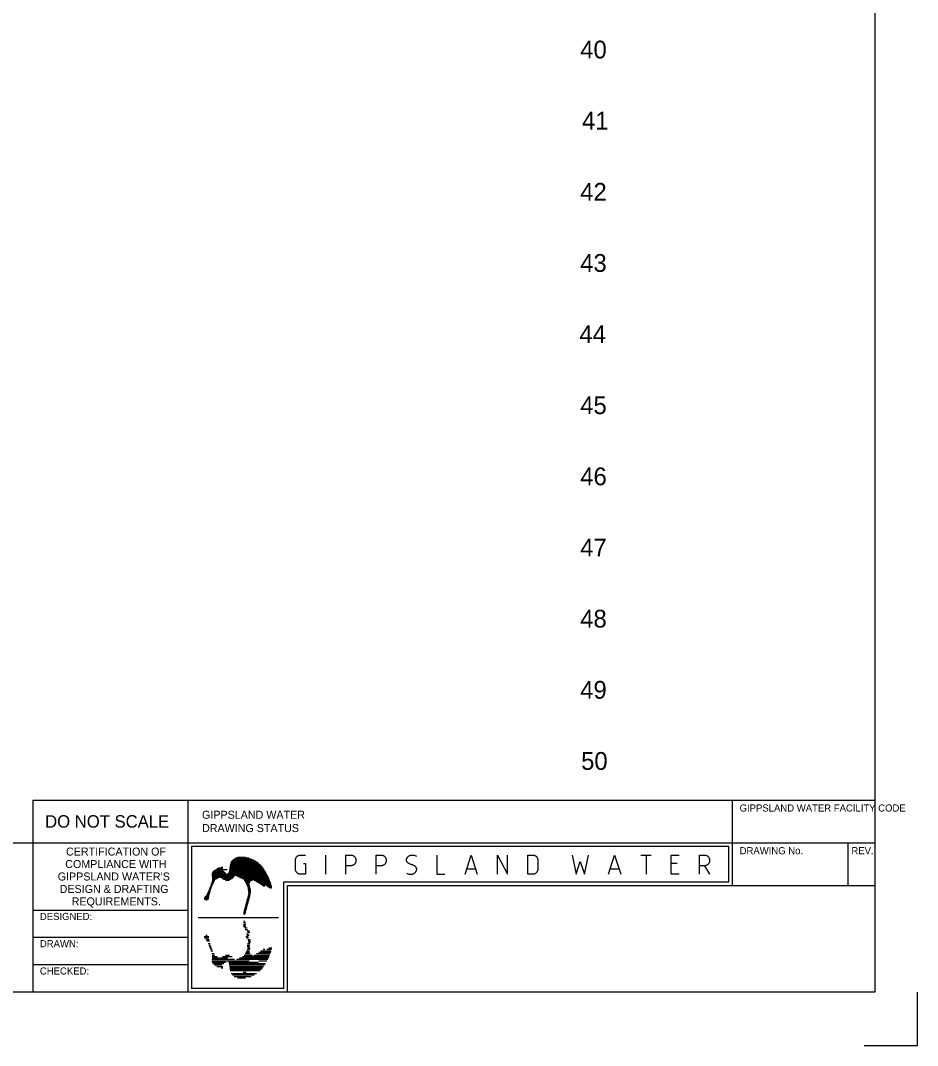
# Model space of a CAD drawing. Extents: x 0 to 841, y 0 to 594.
# Drawn here: x 589 to 841, y 0 to 288.2 of the extents above; entities that cross this region are included whole.
import ezdxf

# ---------------------------------------------------------------- set-up
doc = ezdxf.new("R2010")
doc.units = 0
doc.layers.add('A1BORDER', color=7, linetype='Continuous')
doc.layers.add('Level 1', color=7, linetype='Continuous')

msp = doc.modelspace()

# ---------------------------------------------------------------- linework, layer by layer
at = {"layer": 'A1BORDER'}
for p, q in [((829, 581), (829, 15)), ((592.5, 69), (592.5, 15)), ((592.5, 69), (829, 69)), ((636, 69), (636, 15)), ((789, 45), (789, 69)), ((28, 57), (829, 57)), ((637, 56), (788, 56)), ((637, 56), (637, 16)), ((788, 46), (788, 56)), ((821.5, 45), (821.5, 57)), ((648.37, 51.92), (655, 51.92)), ((648.53, 52.12), (654.64, 52.12)), ((648.74, 52.32), (654.24, 52.32)), ((649.02, 52.52), (653.76, 52.52)), ((649.39, 52.72), (653.15, 52.72)), ((650.01, 52.92), (652.2, 52.92)), ((643.26, 49.12), (645.9, 49.12)), ((643.54, 49.32), (645.57, 49.32)), ((643.85, 49.52), (647.09, 49.52)), ((644.18, 49.72), (645.89, 49.72)), ((644.54, 49.92), (645.36, 49.92)), ((645.37, 50.12), (645.86, 50.12)), ((647.63, 49.12), (657.68, 49.12)), ((647.66, 49.32), (657.57, 49.32)), ((647.69, 49.52), (657.44, 49.52)), ((647.71, 49.72), (657.31, 49.72)), ((647.75, 49.92), (657.17, 49.92)), ((647.78, 50.12), (657.02, 50.12)), ((647.81, 50.32), (656.86, 50.32)), ((647.85, 50.52), (656.69, 50.52)), ((647.88, 50.72), (656.5, 50.72)), ((647.91, 50.92), (656.3, 50.92)), ((647.96, 51.12), (656.08, 51.12)), ((648.03, 51.32), (655.85, 51.32)), ((648.12, 51.52), (655.59, 51.52)), ((648.23, 51.72), (655.31, 51.72)), ((642.73, 48.12), (658.25, 48.12)), ((642.74, 47.92), (658.35, 47.92)), ((642.75, 48.32), (646.79, 48.32)), ((642.79, 47.72), (649.08, 47.72)), ((642.79, 46.12), (643.4, 46.12)), ((642.81, 48.52), (646.55, 48.52)), ((642.83, 47.52), (648.95, 47.52)), ((642.84, 46.32), (643.5, 46.32)), ((642.85, 47.31), (644.88, 47.31)), ((642.87, 47.12), (644.57, 47.12)), ((642.87, 46.52), (643.6, 46.52)), ((642.88, 46.92), (644.23, 46.92)), ((642.88, 46.72), (643.83, 46.72)), ((642.9, 48.72), (646.37, 48.72)), ((643.04, 48.92), (646.16, 48.92)), ((645.14, 47.31), (648.83, 47.31)), ((645.49, 47.12), (648.67, 47.12)), ((645.76, 46.92), (648.42, 46.92)), ((646.05, 46.72), (648.11, 46.72)), ((646.62, 46.52), (647.67, 46.52)), ((647.19, 48.32), (658.14, 48.32)), ((647.42, 48.52), (658.03, 48.52)), ((647.54, 48.72), (657.92, 48.72)), ((647.61, 48.92), (657.8, 48.92)), ((649.72, 47.72), (658.45, 47.72)), ((650.12, 47.52), (658.55, 47.52)), ((650.48, 47.31), (658.64, 47.31)), ((650.87, 47.12), (658.73, 47.12)), ((651.36, 46.92), (658.82, 46.92)), ((651.76, 46.72), (658.9, 46.72)), ((651.88, 46.52), (654.15, 46.52)), ((651.99, 46.32), (653.71, 46.32)), ((652.1, 46.12), (653.52, 46.12)), ((654.57, 46.52), (658.99, 46.52)), ((655, 46.32), (659.07, 46.32)), ((655.31, 46.12), (659.14, 46.12)), ((641.73, 43.32), (642.3, 43.32)), ((641.82, 43.51), (642.35, 43.51)), ((641.91, 43.72), (642.41, 43.72)), ((641.99, 43.92), (642.48, 43.92)), ((642.06, 44.12), (642.55, 44.12)), ((642.13, 44.32), (642.62, 44.32)), ((642.21, 44.52), (642.69, 44.52)), ((642.28, 44.72), (642.76, 44.72)), ((642.35, 44.92), (642.83, 44.92)), ((642.43, 45.12), (642.9, 45.12)), ((642.5, 45.32), (643, 45.32)), ((642.57, 45.52), (643.1, 45.52)), ((642.65, 45.72), (643.2, 45.72)), ((642.72, 45.92), (643.3, 45.92)), ((652.2, 45.92), (653.4, 45.92)), ((652.31, 45.72), (653.33, 45.72)), ((652.41, 45.52), (653.31, 45.52)), ((652.5, 45.32), (653.34, 45.32)), ((652.6, 45.12), (653.38, 45.12)), ((652.69, 44.92), (653.41, 44.92)), ((652.78, 44.72), (653.44, 44.72)), ((652.83, 44.52), (653.48, 44.52)), ((652.86, 44.32), (653.53, 44.32)), ((652.89, 44.12), (653.57, 44.12)), ((652.91, 43.92), (653.62, 43.92)), ((652.94, 43.72), (653.67, 43.72)), ((652.97, 43.51), (653.71, 43.51)), ((653, 43.32), (653.69, 43.32)), ((655.62, 45.92), (659.22, 45.92)), ((655.93, 45.72), (659.29, 45.72)), ((656.24, 45.52), (659.35, 45.52)), ((656.55, 45.32), (659.42, 45.32)), ((656.86, 45.12), (657.74, 45.12)), ((657.17, 44.92), (657.68, 44.92)), ((657.51, 44.72), (657.54, 44.72)), ((657.91, 45.12), (659.48, 45.12)), ((658.19, 44.92), (659.54, 44.92)), ((658.47, 44.72), (659.59, 44.72)), ((658.75, 44.52), (659.58, 44.52)), ((659.02, 44.32), (659.47, 44.32)), ((663, 46), (788, 46)), ((663, 16), (663, 46)), ((664, 45), (829, 45)), ((664, 15), (664, 45)), ((640.62, 41.32), (641.88, 41.32)), ((640.63, 41.52), (641.93, 41.52)), ((640.72, 41.12), (641.73, 41.12)), ((640.73, 41.72), (641.95, 41.72)), ((640.9, 41.92), (641.97, 41.92)), ((641.03, 40.92), (641.43, 40.92)), ((641.1, 42.12), (642, 42.12)), ((641.25, 42.31), (642.04, 42.31)), ((641.37, 42.52), (642.09, 42.52)), ((641.46, 42.72), (642.15, 42.72)), ((641.55, 42.92), (642.2, 42.92)), ((641.64, 43.12), (642.25, 43.12)), ((652.47, 40.52), (653.1, 40.52)), ((652.52, 40.72), (653.15, 40.72)), ((652.57, 40.92), (653.2, 40.92)), ((652.63, 41.12), (653.26, 41.12)), ((652.68, 41.32), (653.31, 41.32)), ((652.74, 41.52), (653.37, 41.52)), ((652.79, 41.72), (653.41, 41.72)), ((652.85, 41.92), (653.45, 41.92)), ((652.9, 42.12), (653.49, 42.12)), ((652.95, 42.31), (653.53, 42.31)), ((652.99, 42.52), (653.57, 42.52)), ((653.02, 43.12), (653.67, 43.12)), ((653.03, 42.72), (653.61, 42.72)), ((653.05, 42.92), (653.64, 42.92)), ((636, 38), (592.5, 38)), ((651.65, 37.52), (652.28, 37.52)), ((651.71, 37.72), (652.34, 37.72)), ((651.76, 37.92), (652.39, 37.92)), ((651.82, 38.12), (652.44, 38.12)), ((651.87, 38.32), (652.5, 38.32)), ((651.92, 38.52), (652.55, 38.52)), ((651.98, 38.72), (652.61, 38.72)), ((652.03, 38.92), (652.66, 38.92)), ((652.09, 39.12), (652.72, 39.12)), ((652.14, 39.32), (652.77, 39.32)), ((652.2, 39.52), (652.82, 39.52)), ((652.25, 39.72), (652.88, 39.72)), ((652.3, 39.92), (652.93, 39.92)), ((652.36, 40.12), (652.99, 40.12)), ((652.41, 40.32), (653.04, 40.32)), ((638.93, 35.98), (661.47, 35.98)), ((651.63, 37.32), (652.23, 37.32)), ((651.63, 34.64), (652.23, 34.64)), ((651.64, 37.12), (652.17, 37.12)), ((651.79, 36.92), (651.9, 36.92)), ((651.79, 35.04), (651.9, 35.04)), ((651.54, 33.84), (652.17, 33.84)), ((651.65, 33.44), (652.28, 33.44)), ((651.71, 34.24), (652.34, 34.24)), ((652.03, 33.04), (652.66, 33.04)), ((652.14, 32.64), (652.77, 32.64)), ((652.66, 32.24), (653.29, 32.24)), ((652.77, 31.84), (653.4, 31.84)), ((636, 30.34), (592.5, 30.34)), ((640.62, 30.64), (641.88, 30.64)), ((640.73, 30.24), (641.95, 30.24)), ((641.03, 31.04), (641.43, 31.04)), ((641.1, 29.84), (642, 29.84)), ((641.37, 29.44), (642.09, 29.44)), ((652.34, 30.64), (652.97, 30.64)), ((652.45, 30.24), (653.07, 30.24)), ((652.47, 31.44), (653.1, 31.44)), ((652.57, 31.04), (653.2, 31.04)), ((652.9, 29.84), (653.49, 29.84)), ((652.99, 29.44), (653.57, 29.44)), ((653.05, 29.04), (653.64, 29.04)), ((641.73, 28.64), (642.3, 28.64)), ((641.91, 28.24), (642.41, 28.24)), ((642.06, 27.84), (642.55, 27.84)), ((642.21, 27.44), (642.69, 27.44)), ((642.35, 27.04), (642.83, 27.04)), ((642.5, 26.64), (643, 26.64)), ((652.31, 26.24), (653.33, 26.24)), ((652.5, 26.64), (653.34, 26.64)), ((652.66, 27.84), (653.35, 27.84)), ((652.69, 27.04), (653.41, 27.04)), ((652.72, 28.24), (653.44, 28.24)), ((652.77, 28.64), (653.46, 28.64)), ((652.83, 27.44), (653.48, 27.44)), ((655.93, 26.24), (659.29, 26.24)), ((656.55, 26.64), (659.42, 26.64)), ((657.17, 27.04), (657.68, 27.04)), ((658.19, 27.04), (659.54, 27.04)), ((658.75, 27.44), (659.58, 27.44)), ((642.73, 23.84), (653.27, 23.84)), ((642.79, 25.84), (643.4, 25.84)), ((642.79, 24.24), (649.08, 24.24)), ((642.81, 23.44), (646.55, 23.44)), ((642.85, 24.65), (644.88, 24.65)), ((642.87, 25.44), (643.6, 25.44)), ((642.88, 25.04), (644.23, 25.04)), ((645.14, 24.65), (647.18, 24.65)), ((645.76, 25.04), (648.42, 25.04)), ((646.62, 25.44), (647.67, 25.44)), ((647.42, 23.44), (655.89, 23.44)), ((649.72, 24.24), (658.45, 24.24)), ((650.48, 24.65), (658.64, 24.65)), ((651.36, 25.04), (658.82, 25.04)), ((651.88, 25.44), (654.15, 25.44)), ((652.1, 25.84), (653.52, 25.84)), ((654.57, 25.44), (658.99, 25.44)), ((655.31, 25.84), (659.14, 25.84)), ((655.94, 23.84), (658.25, 23.84)), ((636, 22.67), (592.5, 22.67)), ((643.04, 23.04), (646.16, 23.04)), ((643.54, 22.64), (645.57, 22.64)), ((644.18, 22.24), (645.89, 22.24)), ((645.37, 21.84), (645.86, 21.84)), ((647.61, 23.04), (657.8, 23.04)), ((647.66, 22.64), (657.57, 22.64)), ((647.71, 22.24), (657.31, 22.24)), ((647.78, 21.84), (657.02, 21.84)), ((647.85, 21.44), (656.69, 21.44)), ((647.91, 21.04), (656.3, 21.04)), ((648.23, 20.24), (655.31, 20.24)), ((651.57, 20.64), (652.44, 20.64)), ((648.53, 19.84), (654.64, 19.84)), ((649.02, 19.44), (653.76, 19.44)), ((650.01, 19.04), (652.2, 19.04)), ((829, 15), (28, 15)), ((663, 16), (637, 16)), ((829, 15), (829, 15)), ((841, 0), (841, 15)), ((826, 0), (841, 0))]:
    msp.add_line(p, q, dxfattribs=at)
for points in [[(668.49, 51.15), (669.06, 51.15), (669.06, 48.16), (667.64, 48.16), (667.51, 48.16), (667.39, 48.18), (667.28, 48.21), (667.15, 48.25), (667.04, 48.3), (666.93, 48.36), (666.82, 48.43), (666.73, 48.51), (666.64, 48.6), (666.55, 48.7), (666.48, 48.8), (666.41, 48.91), (666.35, 49.02), (666.31, 49.14), (666.27, 49.27), (666.24, 49.39), (666.22, 49.52), (666.22, 49.66), (666.22, 52.05), (666.22, 52.18), (666.24, 52.31), (666.27, 52.43), (666.31, 52.56), (666.35, 52.67), (666.41, 52.79), (666.48, 52.9), (666.55, 53), (666.64, 53.1), (666.73, 53.19), (666.82, 53.27), (666.93, 53.34), (667.04, 53.4), (667.15, 53.45), (667.28, 53.49), (667.39, 53.52), (667.51, 53.54), (667.64, 53.54), (669.06, 53.54)], [(674.74, 48.16), (674.74, 53.54)], [(680.42, 48.16), (680.42, 53.54), (681.84, 53.54), (681.96, 53.54), (682.08, 53.52), (682.2, 53.49), (682.32, 53.45), (682.43, 53.4), (682.54, 53.34), (682.65, 53.27), (682.74, 53.19), (682.84, 53.1), (682.92, 53), (682.99, 52.9), (683.06, 52.79), (683.12, 52.67), (683.17, 52.56), (683.21, 52.43), (683.23, 52.31), (683.25, 52.18), (683.26, 52.05), (683.25, 51.91), (683.23, 51.78), (683.21, 51.66), (683.17, 51.53), (683.12, 51.42), (683.06, 51.3), (682.99, 51.19), (682.92, 51.09), (682.84, 50.99), (682.74, 50.9), (682.65, 50.82), (682.54, 50.75), (682.43, 50.69), (682.32, 50.64), (682.2, 50.6), (682.08, 50.57), (681.96, 50.55), (681.84, 50.55), (680.42, 50.55)], [(688.93, 48.16), (688.93, 53.54), (690.35, 53.54), (690.47, 53.54), (690.59, 53.52), (690.71, 53.49), (690.83, 53.45), (690.94, 53.4), (691.05, 53.34), (691.16, 53.27), (691.26, 53.19), (691.35, 53.1), (691.43, 53), (691.51, 52.9), (691.57, 52.79), (691.63, 52.67), (691.68, 52.56), (691.72, 52.43), (691.75, 52.31), (691.76, 52.18), (691.77, 52.05), (691.76, 51.91), (691.75, 51.78), (691.72, 51.66), (691.68, 51.53), (691.63, 51.42), (691.57, 51.3), (691.51, 51.19), (691.43, 51.09), (691.35, 50.99), (691.26, 50.9), (691.16, 50.82), (691.05, 50.75), (690.94, 50.69), (690.83, 50.64), (690.71, 50.6), (690.59, 50.57), (690.47, 50.55), (690.35, 50.55), (688.93, 50.55)], [(697.45, 48.46), (697.67, 48.36), (697.9, 48.27), (698.12, 48.21), (698.36, 48.17), (698.6, 48.16), (698.84, 48.16), (698.87, 48.16), (699.03, 48.18), (699.18, 48.21), (699.33, 48.26), (699.48, 48.32), (699.62, 48.4), (699.72, 48.46), (699.81, 48.53), (699.9, 48.61), (699.98, 48.69), (700.05, 48.78), (700.11, 48.88), (700.17, 48.99), (700.22, 49.09), (700.25, 49.21), (700.28, 49.32), (700.29, 49.36), (700.3, 49.44), (700.3, 49.52), (700.3, 49.61), (700.29, 49.69), (700.27, 49.77), (700.25, 49.86), (700.22, 49.93), (700.18, 50.01), (700.14, 50.09), (700.09, 50.15), (700.04, 50.21), (700.01, 50.25), (699.85, 50.39), (699.69, 50.51), (699.52, 50.61), (699.34, 50.7), (699.15, 50.78), (698.95, 50.83), (698.87, 50.85), (698.68, 50.9), (698.49, 50.96), (698.3, 51.04), (698.12, 51.14), (697.96, 51.26), (697.8, 51.39), (697.73, 51.45), (697.67, 51.51), (697.62, 51.57), (697.58, 51.64), (697.53, 51.71), (697.5, 51.79), (697.47, 51.87), (697.46, 51.95), (697.44, 52.04), (697.43, 52.12), (697.43, 52.21), (697.44, 52.29), (697.45, 52.35), (697.47, 52.46), (697.51, 52.58), (697.55, 52.69), (697.61, 52.79), (697.67, 52.89), (697.74, 52.99), (697.82, 53.07), (697.9, 53.15), (697.99, 53.23), (698.02, 53.24), (698.15, 53.33), (698.3, 53.4), (698.44, 53.45), (698.6, 53.5), (698.75, 53.52), (698.87, 53.54), (699.11, 53.55), (699.35, 53.53), (699.58, 53.49), (699.82, 53.43), (700.04, 53.35), (700.27, 53.25)], [(705.96, 53.54), (705.96, 48.16), (708.23, 48.16)], [(713.91, 48.16), (715.61, 53.54), (717.32, 48.16)], [(722.99, 48.16), (722.99, 53.54), (725.83, 48.16), (725.83, 53.54)], [(731.52, 48.16), (731.52, 53.54), (732.94, 53.54), (733.06, 53.54), (733.18, 53.52), (733.3, 53.49), (733.42, 53.45), (733.53, 53.4), (733.64, 53.34), (733.75, 53.27), (733.84, 53.19), (733.94, 53.1), (734.02, 53), (734.09, 52.9), (734.16, 52.79), (734.22, 52.67), (734.27, 52.56), (734.31, 52.43), (734.33, 52.31), (734.35, 52.18), (734.36, 52.05), (734.36, 49.66), (734.35, 49.52), (734.33, 49.39), (734.31, 49.27), (734.27, 49.14), (734.22, 49.02), (734.16, 48.91), (734.09, 48.8), (734.02, 48.7), (733.94, 48.6), (733.84, 48.51), (733.75, 48.43), (733.64, 48.36), (733.53, 48.3), (733.42, 48.25), (733.3, 48.21), (733.18, 48.18), (733.06, 48.16), (732.94, 48.16), (731.52, 48.16)], [(744.01, 53.54), (745.14, 48.16), (746.28, 51.75), (747.41, 48.16), (748.55, 53.54)], [(754.22, 48.16), (755.92, 53.54), (757.63, 48.16)], [(763.31, 53.54), (766.15, 53.54)], [(764.73, 53.54), (764.73, 48.16)], [(774.09, 48.16), (771.82, 48.16), (771.82, 53.54), (774.09, 53.54)], [(779.78, 48.16), (779.78, 53.54), (781.2, 53.54), (781.32, 53.54), (781.44, 53.52), (781.56, 53.49), (781.68, 53.45), (781.79, 53.4), (781.9, 53.34), (782.01, 53.27), (782.1, 53.19), (782.2, 53.1), (782.28, 53), (782.35, 52.9), (782.42, 52.79), (782.48, 52.67), (782.53, 52.56), (782.56, 52.43), (782.59, 52.31), (782.61, 52.18), (782.61, 52.05), (782.61, 51.91), (782.59, 51.78), (782.56, 51.66), (782.53, 51.53), (782.48, 51.42), (782.42, 51.3), (782.35, 51.19), (782.28, 51.09), (782.2, 50.99), (782.1, 50.9), (782.01, 50.82), (781.9, 50.75), (781.79, 50.69), (781.68, 50.64), (781.56, 50.6), (781.44, 50.57), (781.32, 50.55), (781.2, 50.55), (779.78, 50.55)], [(714.48, 49.66), (716.75, 49.66)], [(754.79, 49.66), (757.06, 49.66)], [(773.53, 51.15), (771.82, 51.15)], [(781.2, 50.55), (782.61, 48.16)]]:
    msp.add_lwpolyline(points, dxfattribs=at)

# ---------------------------------------------------------------- texts
for s, height, p in [('GIPPSLAND WATER FACILITY CODE', 2, (791.03, 65.77)), ('DO NOT SCALE', 3.5, (595.92, 61.25)), ('GIPPSLAND WATER', 2.25, (640, 63.75)), ('DRAWING STATUS', 2.25, (640, 60)), ('CERTIFICATION OF', 2.25, (601.79, 53.39)), ('DRAWING No.', 2, (791.03, 53.77)), ('REV.', 2, (822.43, 53.77)), ('COMPLIANCE WITH', 2.25, (601.57, 49.89)), ("GIPPSLAND WATER'S", 2.25, (599.45, 46.39)), ('DESIGN & DRAFTING', 2.25, (600, 42.89)), ('REQUIREMENTS.', 2.25, (603.37, 39.39)), ('DESIGNED:', 2, (594.44, 35.29)), ('DRAWN:', 2, (594.44, 27.62)), ('CHECKED:', 2, (594.44, 19.95))]:
    msp.add_text(s, height=height, dxfattribs=at).set_placement(p)
at = {"layer": 'Level 1'}
for s, p in [('40', (746.26, 277.5)), ('41', (746.76, 257.5)), ('42', (746.26, 237.5)), ('43', (746.26, 217.5)), ('44', (746.02, 197.5)), ('45', (746.26, 177.5)), ('46', (746.26, 157.5)), ('47', (746.26, 137.5)), ('48', (746.26, 117.5)), ('49', (746.26, 97.5)), ('50', (746.51, 77.5))]:
    msp.add_text(s, height=5, dxfattribs=at).set_placement(p)

doc.saveas('drawing.dxf')
